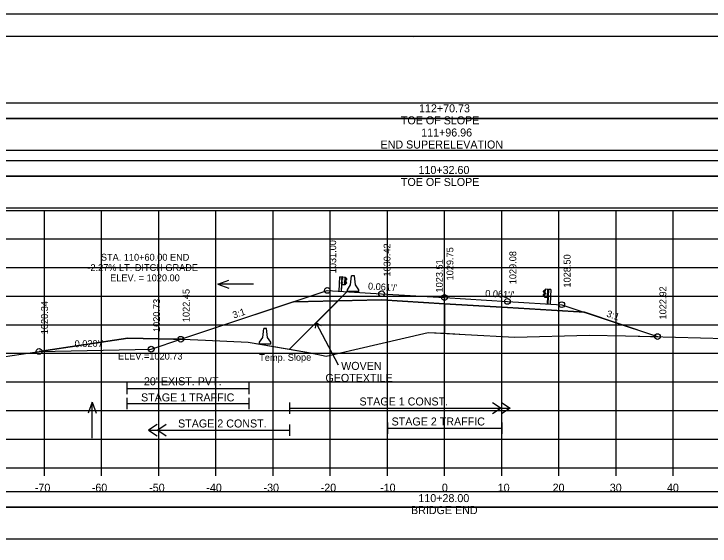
# Model space of a CAD drawing. Extents: x 1370565 to 1374448, y 301010 to 304637.
# Drawn here: x 1370659.7 to 1370781.5, y 302410.8 to 302503.9 of the extents above; entities that cross this region are included whole.
import ezdxf

# ---------------------------------------------------------------- set-up
doc = ezdxf.new("R2010")
doc.units = 0
for name, color, linetype in [('Default', 7, 'Continuous'), ('R_Alt Surface', 7, 'Continuous'), ('R_Axis', 7, 'Continuous'), ('R_Axis Annot', 7, 'Continuous'), ('R_Border', 7, 'Continuous'), ('R_Contours', 7, 'Continuous'), ('R_Drive', 7, 'Continuous'), ('R_Exist Surface', 7, 'Continuous'), ('R_Fin Surface', 7, 'Continuous'), ('R_Grid', 7, 'Continuous'), ('R_MOT', 7, 'Continuous'), ('R_No Plot', 7, 'Continuous'), ('R_Proposed Road', 7, 'Continuous'), ('R_Water', 7, 'Continuous'), ('R_Water Annot', 7, 'Continuous'), ('R_Xsect Elev', 7, 'Continuous'), ('R_Xsect Slope', 7, 'Continuous')]:
    doc.layers.add(name, color=color, linetype=linetype)

# ---------------------------------------------------------------- blocks, each defined once
blk = doc.blocks.new('MEDBAR_P')
at = {"layer": 'R_MOT'}
for p, q in [((-2.46, -0.98), (-1.63, 6.93)), ((-0.38, 6.93), (-1.63, 6.93)), ((0.87, 6.93), (-0.38, 6.93)), ((1.71, -0.98), (0.87, 6.93)), ((-5.37, -6.81), (-5.34, -5.15)), ((-5.34, -5.15), (-2.46, -0.98)), ((4.66, -5.15), (1.71, -0.98)), ((4.63, -6.81), (4.66, -5.15)), ((4.63, -6.81), (-5.37, -6.81))]:
    blk.add_line(p, q, dxfattribs=at)
blk = doc.blocks.new('GUARDRAIL LT_P')
at = {"layer": 'R_Proposed Road'}
for p, q in [((0, 2.52), (0, 0)), ((0.03, 2.52), (0.03, 0)), ((0.53, 2.52), (0.46, 2.51)), ((0.49, 0), (0.49, 2.52)), ((0.53, 2.52), (0.52, 2.52)), ((1.02, 1.15), (1.02, 2.51)), ((0.39, 1.42), (0.39, 1.51)), ((0.4, 2.11), (0.4, 2.2)), ((0.45, 1.53), (0.4, 1.53)), ((0.45, 1.49), (0.4, 1.49)), ((0.45, 1.43), (0.4, 1.43)), ((0.45, 1.43), (0.4, 1.43)), ((0.45, 1.4), (0.4, 1.4)), ((0.46, 2.21), (0.41, 2.21)), ((0.46, 2.18), (0.41, 2.18)), ((0.46, 2.12), (0.41, 2.12)), ((0.46, 2.12), (0.41, 2.12)), ((0.46, 2.09), (0.41, 2.09)), ((0.45, 1.4), (0.45, 1.53)), ((0.46, 2.09), (0.46, 2.21)), ((0.58, 2.15), (0.52, 2.15)), ((0.58, 1.46), (0.52, 1.46)), ((0.53, 2.21), (0.58, 2.21)), ((0.53, 2.08), (0.58, 2.08)), ((0.58, 1.53), (0.53, 1.53)), ((0.58, 1.4), (0.53, 1.4)), ((0.58, 2.21), (0.58, 2.08)), ((0.58, 1.4), (0.58, 1.53)), ((1.01, 1.89), (0.96, 1.89)), ((0.96, 1.78), (0.96, 1.88)), ((1.01, 1.86), (0.96, 1.86)), ((1.01, 1.8), (0.96, 1.8)), ((1.01, 1.77), (0.96, 1.77)), ((1.01, 1.8), (0.97, 1.8)), ((1.01, 1.77), (1.01, 1.89)), ((1.05, 1.31), (1.16, 1.37)), ((1.17, 2.3), (1.06, 2.36)), ((1.16, 2.29), (1.06, 2.34)), ((1.06, 1.77), (1.06, 1.9)), ((1.06, 1.29), (1.17, 1.35)), ((1.09, 1.77), (1.09, 1.9)), ((1.26, 1.6), (1.1, 1.69)), ((1.11, 1.97), (1.28, 2.07)), ((1.12, 1.95), (1.29, 2.05)), ((1.27, 1.62), (1.12, 1.71)), ((1.28, 2.18), (1.16, 2.29)), ((1.16, 1.37), (1.29, 1.48)), ((1.3, 2.2), (1.17, 2.3)), ((1.17, 1.35), (1.3, 1.46)), ((0.52, 1.15), (0.49, 1.15))]:
    blk.add_line(p, q, dxfattribs=at)
blk.add_lwpolyline([(0, 2.52), (0.46, 2.51), (0.45, 0)], dxfattribs=at)
for points in [[(1.05, 2.52), (1.05, 1.15), (0.52, 1.15), (0.53, 2.52)], [(0.39, 1.49), (0.39, 1.43), (0.36, 1.43), (0.36, 1.49)], [(0.4, 2.18), (0.4, 2.12), (0.37, 2.12), (0.37, 2.18)], [(0.44, 1.55), (0.44, 1.38), (0.45, 1.38), (0.45, 1.55)], [(0.45, 2.23), (0.45, 2.07), (0.46, 2.07), (0.46, 2.23)], [(0.58, 2.21), (0.58, 2.08), (0.53, 2.08), (0.53, 2.21)], [(0.58, 1.53), (0.58, 1.4), (0.53, 1.4), (0.53, 1.53)], [(0.95, 1.86), (0.95, 1.8), (0.93, 1.8), (0.93, 1.86)], [(1.01, 1.91), (1.01, 1.75), (1.02, 1.75), (1.02, 1.91)]]:
    blk.add_lwpolyline(points, close=True, dxfattribs=at)
for centre, radius, start, end in [((0.41, 1.51), 0.022, 134.5745, 222.2244), ((0.48, 1.46), 0.0922, 159.7423, 200.2577), ((0.41, 1.41), 0.025, 140.9334, 216.6234), ((0.42, 2.2), 0.022, 134.5745, 222.2244), ((0.49, 2.15), 0.0922, 159.7423, 200.2577), ((0.43, 2.1), 0.025, 140.9334, 216.6234), ((0.98, 1.88), 0.022, 134.5745, 222.2244), ((1.05, 1.83), 0.0922, 159.7423, 200.2577), ((0.98, 1.78), 0.025, 140.9334, 216.6234), ((1.15, 1.89), 0.0865, 118.106, 175.0444), ((1.13, 1.76), 0.0703, 171.7804, 246.8536), ((1.08, 1.83), 0.0453, 282.9554, 86.0697), ((1.15, 1.89), 0.0622, 118.106, 175.0444), ((1.13, 1.76), 0.0462, 171.7804, 246.8536), ((1.22, 1.52), 0.0854, 325.2184, 59.12), ((1.22, 1.52), 0.109, 325.2184, 59.12), ((1.25, 2.13), 0.062, 299.2499, 57.9783), ((1.25, 2.13), 0.0856, 299.2499, 57.9783)]:
    blk.add_arc(centre, radius, start, end, dxfattribs=at)
blk = doc.blocks.new('GUARDRAIL RT_P')
at = {"layer": 'R_Proposed Road'}
for p, q in [((-1.02, 1.15), (-1.02, 2.51)), ((-0.53, 2.52), (-0.52, 2.52)), ((-0.53, 2.52), (-0.46, 2.51)), ((-0.49, 0), (-0.49, 2.52)), ((-0.03, 2.52), (-0.03, 0)), ((0, 2.52), (0, 0)), ((-1.3, 2.2), (-1.17, 2.3)), ((-1.17, 1.35), (-1.3, 1.46)), ((-1.12, 1.95), (-1.29, 2.05)), ((-1.16, 1.37), (-1.29, 1.48)), ((-1.28, 2.18), (-1.16, 2.29)), ((-1.11, 1.97), (-1.28, 2.07)), ((-1.27, 1.62), (-1.12, 1.71)), ((-1.26, 1.6), (-1.1, 1.69)), ((-1.17, 2.3), (-1.06, 2.36)), ((-1.06, 1.29), (-1.17, 1.35)), ((-1.16, 2.29), (-1.06, 2.34)), ((-1.05, 1.31), (-1.16, 1.37)), ((-1.09, 1.77), (-1.09, 1.9)), ((-1.06, 1.77), (-1.06, 1.9)), ((-1.01, 1.77), (-1.01, 1.89)), ((-1.01, 1.89), (-0.96, 1.89)), ((-1.01, 1.86), (-0.96, 1.86)), ((-1.01, 1.8), (-0.97, 1.8)), ((-1.01, 1.8), (-0.96, 1.8)), ((-1.01, 1.77), (-0.96, 1.77)), ((-0.96, 1.78), (-0.96, 1.88)), ((-0.53, 2.21), (-0.58, 2.21)), ((-0.58, 2.21), (-0.58, 2.08)), ((-0.58, 2.15), (-0.52, 2.15)), ((-0.53, 2.08), (-0.58, 2.08)), ((-0.58, 1.4), (-0.58, 1.53)), ((-0.58, 1.53), (-0.53, 1.53)), ((-0.58, 1.46), (-0.52, 1.46)), ((-0.58, 1.4), (-0.53, 1.4)), ((-0.46, 2.09), (-0.46, 2.21)), ((-0.46, 2.21), (-0.41, 2.21)), ((-0.46, 2.18), (-0.41, 2.18)), ((-0.46, 2.12), (-0.41, 2.12)), ((-0.46, 2.12), (-0.41, 2.12)), ((-0.46, 2.09), (-0.41, 2.09)), ((-0.45, 1.4), (-0.45, 1.53)), ((-0.45, 1.53), (-0.4, 1.53)), ((-0.45, 1.49), (-0.4, 1.49)), ((-0.45, 1.43), (-0.4, 1.43)), ((-0.45, 1.43), (-0.4, 1.43)), ((-0.45, 1.4), (-0.4, 1.4)), ((-0.4, 2.11), (-0.4, 2.2)), ((-0.39, 1.42), (-0.39, 1.51)), ((-0.52, 1.15), (-0.49, 1.15))]:
    blk.add_line(p, q, dxfattribs=at)
for points in [[(-1.05, 2.52), (-1.05, 1.15), (-0.52, 1.15), (-0.53, 2.52)], [(-1.01, 1.91), (-1.01, 1.75), (-1.02, 1.75), (-1.02, 1.91)], [(-0.95, 1.86), (-0.95, 1.8), (-0.93, 1.8), (-0.93, 1.86)], [(-0.58, 2.21), (-0.58, 2.08), (-0.53, 2.08), (-0.53, 2.21)], [(-0.58, 1.53), (-0.58, 1.4), (-0.53, 1.4), (-0.53, 1.53)], [(-0.45, 2.23), (-0.45, 2.07), (-0.46, 2.07), (-0.46, 2.23)], [(-0.44, 1.55), (-0.44, 1.38), (-0.45, 1.38), (-0.45, 1.55)], [(-0.4, 2.18), (-0.4, 2.12), (-0.37, 2.12), (-0.37, 2.18)], [(-0.39, 1.49), (-0.39, 1.43), (-0.36, 1.43), (-0.36, 1.49)]]:
    blk.add_lwpolyline(points, close=True, dxfattribs=at)
blk.add_lwpolyline([(0, 2.52), (-0.46, 2.51), (-0.45, 0)], dxfattribs=at)
for centre, radius, start, end in [((-1.25, 2.13), 0.0856, 122.0217, 240.7501), ((-1.22, 1.52), 0.109, 120.88, 214.7816), ((-1.25, 2.13), 0.062, 122.0217, 240.7501), ((-1.22, 1.52), 0.0854, 120.88, 214.7816), ((-1.08, 1.83), 0.0453, 93.9303, 257.0446), ((-1.15, 1.89), 0.0622, 4.9556, 61.894), ((-1.15, 1.89), 0.0865, 4.9556, 61.894), ((-1.13, 1.76), 0.0462, 293.1464, 8.2196), ((-1.13, 1.76), 0.0703, 293.1464, 8.2196), ((-0.98, 1.88), 0.022, 317.7756, 45.4255), ((-1.05, 1.83), 0.0922, 339.7423, 20.2577), ((-0.98, 1.78), 0.025, 323.3766, 39.0666), ((-0.42, 2.2), 0.022, 317.7756, 45.4255), ((-0.49, 2.15), 0.0922, 339.7423, 20.2577), ((-0.43, 2.1), 0.025, 323.3766, 39.0666), ((-0.41, 1.51), 0.022, 317.7756, 45.4255), ((-0.48, 1.46), 0.0922, 339.7423, 20.2577), ((-0.41, 1.41), 0.025, 323.3766, 39.0666)]:
    blk.add_arc(centre, radius, start, end, dxfattribs=at)

msp = doc.modelspace()

# ---------------------------------------------------------------- linework, layer by layer
at = {"layer": 'R_Alt Surface'}
for points in [[(1370708.62, 302453.53), (1370724.03, 302453.84), (1370735.03, 302453.17), (1370746.03, 302452.5), (1370759.5, 302451.68)], [(1370712.49, 302448.88), (1370712.59, 302449.81), (1370713.46, 302449.34)], [(1370716.51, 302442.42), (1370712.59, 302449.81)], [(1370707.94, 302435.91), (1370707.94, 302433.91)], [(1370743.42, 302435.91), (1370744.92, 302434.91), (1370743.42, 302433.91)], [(1370745.02, 302435.91), (1370746.52, 302434.91), (1370745.02, 302433.91)], [(1370707.94, 302434.91), (1370746.52, 302434.91)], [(1370684.76, 302432.05), (1370683.26, 302431.05), (1370684.76, 302430.05)], [(1370686.36, 302432.05), (1370684.86, 302431.05), (1370686.36, 302430.05)], [(1370707.94, 302432.05), (1370707.94, 302430.05)], [(1370725.03, 302432.4), (1370725.03, 302430.4)], [(1370745.03, 302432.4), (1370745.03, 302430.4)], [(1370683.26, 302431.05), (1370707.94, 302431.05)], [(1370725.03, 302431.4), (1370745.03, 302431.4)]]:
    msp.add_lwpolyline(points, dxfattribs=at)
at = {"layer": 'R_Axis'}
for p, q in [((1370585.03, 302424.5), (1370885.03, 302424.5)), ((1370665.03, 302423.1), (1370665.03, 302424.5)), ((1370675.03, 302423.1), (1370675.03, 302424.5)), ((1370685.03, 302423.1), (1370685.03, 302424.5)), ((1370695.03, 302423.1), (1370695.03, 302424.5)), ((1370705.03, 302423.1), (1370705.03, 302424.5)), ((1370715.03, 302423.1), (1370715.03, 302424.5)), ((1370725.03, 302423.1), (1370725.03, 302424.5)), ((1370735.03, 302423.1), (1370735.03, 302424.5)), ((1370745.03, 302423.1), (1370745.03, 302424.5)), ((1370755.03, 302423.1), (1370755.03, 302424.5)), ((1370765.03, 302423.1), (1370765.03, 302424.5)), ((1370775.03, 302423.1), (1370775.03, 302424.5))]:
    msp.add_line(p, q, dxfattribs=at)
for points in [[(1370679.48, 302439.37), (1370679.48, 302437.37)], [(1370700.82, 302439.37), (1370700.82, 302437.37)], [(1370679.48, 302438.37), (1370700.82, 302438.37)], [(1370679.48, 302436.73), (1370679.48, 302434.73)], [(1370700.82, 302436.73), (1370700.82, 302434.73)], [(1370679.48, 302435.73), (1370700.82, 302435.73)]]:
    msp.add_lwpolyline(points, dxfattribs=at)
at = {"layer": 'R_Border'}
for p, q in [((1370577.03, 302499.96), (1370893.21, 302499.96)), ((1370729.55, 302499.7), (1370729.55, 302499.7)), ((1370729.55, 302499.7), (1370729.55, 302499.7))]:
    msp.add_line(p, q, dxfattribs=at)
at = {"layer": 'R_Contours'}
for p, q in [((1370708.62, 302453.53), (1370689.37, 302447.11)), ((1370716.43, 302453.69), (1370707.94, 302445.21)), ((1370707.94, 302445.21), (1370716.43, 302453.69)), ((1370716.43, 302453.69), (1370708.62, 302453.53)), ((1370735.03, 302448.02), (1370735.03, 302453.17)), ((1370735.03, 302453.17), (1370735.03, 302448.02)), ((1370771.81, 302447.58), (1370759.5, 302451.68)), ((1370688.89, 302446.96), (1370687.61, 302446.97))]:
    msp.add_line(p, q, dxfattribs=at)
for points in [[(1370735.03, 302453.17), (1370724.03, 302453.84), (1370716.43, 302453.69)], [(1370759.5, 302451.68), (1370746.03, 302452.5), (1370735.03, 302453.17)], [(1370707.94, 302445.21), (1370711.61, 302444.57), (1370714.32, 302444.01), (1370719.33, 302445.18), (1370732.16, 302448.17), (1370735.03, 302448.02)], [(1370735.03, 302448.02), (1370738.65, 302447.81), (1370747.31, 302447.33), (1370760.36, 302447.68), (1370766.68, 302447.56), (1370771.78, 302447.43)], [(1370687.61, 302446.97), (1370679.63, 302447.18), (1370664.13, 302444.84)], [(1370664.13, 302444.84), (1370683.72, 302445.23), (1370688.89, 302446.96)], [(1370689.39, 302446.95), (1370690.54, 302446.94), (1370693.24, 302446.83), (1370700.66, 302446.46), (1370707.94, 302445.21)]]:
    msp.add_lwpolyline(points, dxfattribs=at)
for centre, start, end in [((1370772.28, 302447.42), 161.5651, 178.5366), ((1370688.89, 302446.96), 359.3269, 18.4349)]:
    msp.add_arc(centre, 0.5, start, end, dxfattribs=at)
at = {"layer": 'R_Drive'}
for points in [[(1370585.23, 302485.56), (1370883.65, 302485.56), (1370883.65, 302488.27), (1370585.23, 302488.27)], [(1370585.23, 302480.04), (1370883.65, 302480.04), (1370883.65, 302485.56), (1370585.23, 302485.56)], [(1370585.23, 302475.46), (1370883.65, 302475.46), (1370883.65, 302478.17), (1370585.23, 302478.17)], [(1370585.23, 302469.94), (1370883.65, 302469.94), (1370883.65, 302475.46), (1370585.23, 302475.46)], [(1370585.82, 302417.6), (1370884.24, 302417.6), (1370884.24, 302420.3), (1370585.82, 302420.3)], [(1370585.82, 302412.08), (1370884.24, 302412.08), (1370884.24, 302417.6), (1370585.82, 302417.6)]]:
    msp.add_lwpolyline(points, close=True, dxfattribs=at)
at = {"layer": 'R_Exist Surface'}
msp.add_lwpolyline([(1370585.03, 302448.71), (1370585.75, 302448.68), (1370589.95, 302448.49), (1370647.79, 302445.6), (1370648.37, 302445.52), (1370657.82, 302443.86), (1370664.13, 302444.84), (1370679.63, 302447.18), (1370687.61, 302446.97), (1370690.54, 302446.94), (1370693.24, 302446.83), (1370700.66, 302446.46), (1370711.61, 302444.57), (1370714.32, 302444.01), (1370719.33, 302445.18), (1370732.16, 302448.17), (1370738.65, 302447.81), (1370747.31, 302447.33), (1370760.36, 302447.68), (1370766.68, 302447.56), (1370784.21, 302447.12)], dxfattribs=at)
at = {"layer": 'R_Fin Surface'}
msp.add_line((1370718.03, 302455.29), (1370707.94, 302445.21), dxfattribs=at)
msp.add_lwpolyline([(1370664.11, 302444.84), (1370683.72, 302445.23), (1370688.89, 302446.96), (1370714.53, 302455.5), (1370724.03, 302454.92), (1370735.03, 302454.25), (1370746.03, 302453.58), (1370755.53, 302453.01), (1370772.28, 302447.42)], dxfattribs=at)
at = {"layer": 'R_Grid'}
for p, q in [((1370585.03, 302469.5), (1370885.03, 302469.5)), ((1370665.03, 302424.5), (1370665.03, 302469.5)), ((1370675.03, 302424.5), (1370675.03, 302469.5)), ((1370685.03, 302424.5), (1370685.03, 302469.5)), ((1370695.03, 302424.5), (1370695.03, 302469.5)), ((1370705.03, 302424.5), (1370705.03, 302469.5)), ((1370715.03, 302424.5), (1370715.03, 302469.5)), ((1370725.03, 302424.5), (1370725.03, 302469.5)), ((1370735.03, 302424.5), (1370735.03, 302469.5)), ((1370745.03, 302424.5), (1370745.03, 302469.5)), ((1370755.03, 302424.5), (1370755.03, 302469.5)), ((1370765.03, 302424.5), (1370765.03, 302469.5)), ((1370775.03, 302424.5), (1370775.03, 302469.5)), ((1370585.03, 302464.5), (1370885.03, 302464.5)), ((1370585.03, 302459.5), (1370885.03, 302459.5)), ((1370585.03, 302454.5), (1370885.03, 302454.5)), ((1370585.03, 302449.5), (1370885.03, 302449.5)), ((1370585.03, 302444.5), (1370885.03, 302444.5)), ((1370585.03, 302439.5), (1370885.03, 302439.5)), ((1370585.03, 302434.5), (1370885.03, 302434.5)), ((1370585.03, 302429.5), (1370885.03, 302429.5)), ((1370585.03, 302424.5), (1370885.03, 302424.5))]:
    msp.add_line(p, q, dxfattribs=at)
at = {"layer": 'R_No Plot'}
msp.add_line((1370564.63, 302503.86), (1370897.96, 302503.86), dxfattribs=at)
for points in [[(1370564.62, 302503.86), (1370897.96, 302503.86), (1370897.96, 302290.52), (1370564.62, 302290.52)], [(1370810.95, 302499.96), (1370830.57, 302499.96), (1370830.57, 302490.08), (1370846.68, 302490.08), (1370869.88, 302490.08), (1370869.88, 302457.41), (1370893.09, 302457.41), (1370893.21, 302294.5), (1370577.03, 302294.5), (1370577.03, 302499.96)]]:
    msp.add_lwpolyline(points, close=True, dxfattribs=at)
for centre in [(1370714.53, 302455.5), (1370714.53, 302455.5), (1370724.03, 302454.92), (1370735.03, 302454.25), (1370746.03, 302453.58), (1370755.53, 302453.01), (1370755.53, 302453.01), (1370688.89, 302446.96), (1370772.28, 302447.42), (1370664.11, 302444.84), (1370683.72, 302445.23)]:
    msp.add_circle(centre, 0.5, dxfattribs=at)
at = {"layer": 'R_Water Annot'}
for p, q in [((1370695.36, 302456.61), (1370697.28, 302457.31)), ((1370701.64, 302456.61), (1370695.36, 302456.61)), ((1370695.36, 302456.61), (1370697.28, 302455.91)), ((1370673.4, 302435.94), (1370672.7, 302434.01)), ((1370673.4, 302429.65), (1370673.4, 302435.94)), ((1370673.4, 302435.94), (1370674.1, 302434.01))]:
    msp.add_line(p, q, dxfattribs=at)
at = {"layer": 'R_Xsect Elev'}
msp.add_line((1370735.03, 302448.02), (1370735.03, 302461.39), dxfattribs=at)

# ---------------------------------------------------------------- block references
at = {"layer": 'Default'}
for name, p, rotation in [('GUARDRAIL LT_P', (1370716.52, 302455.38), -2.79108977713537), ('GUARDRAIL RT_P', (1370753.53, 302453.13), -2.8654870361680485)]:
    msp.add_blockref(name, p, dxfattribs=dict(at, rotation=rotation))
at = {"layer": 'R_Fin Surface', "xscale": 0.2, "yscale": 0.20000000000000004}
for p in [(1370719.1, 302456.65), (1370703.74, 302447.48)]:
    msp.add_blockref('MEDBAR_P', p, dxfattribs=at)

# ---------------------------------------------------------------- texts
at = {"layer": 'R_Axis Annot'}
for s, p in [('112+70.73', (1370730.57, 302486.65)), ('TOE OF SLOPE', (1370727.4, 302484.55)), ('111+96.96', (1370730.95, 302482.42)), ('END SUPERELEVATION', (1370723.84, 302480.32)), ('110+32.60', (1370730.48, 302475.87)), ('TOE OF SLOPE', (1370727.4, 302473.77)), ('WOVEN ', (1370716.95, 302441.6)), ("20' EXIST. PVT.", (1370682.45, 302438.92)), ('GEOTEXTILE', (1370714.2, 302439.5)), ('-70', (1370663.37, 302420.3)), ('-60', (1370673.33, 302420.3)), ('-50', (1370683.37, 302420.3)), ('-40', (1370693.37, 302420.3)), ('-30', (1370703.37, 302420.3)), ('-20', (1370713.37, 302420.3)), ('-10', (1370723.76, 302420.3)), ('0', (1370734.57, 302420.3)), ('10', (1370744.34, 302420.3)), ('20', (1370753.94, 302420.3)), ('30', (1370763.94, 302420.3)), ('40', (1370773.94, 302420.3)), ('110+28.00', (1370730.46, 302418.48)), ('BRIDGE END', (1370729.17, 302416.38))]:
    msp.add_text(s, height=1.4, dxfattribs=at).set_placement(p)
at = {"layer": 'R_Water'}
for s, p in [('STAGE 1 TRAFFIC', (1370681.94, 302436.09)), ('STAGE 1 CONST.', (1370720.16, 302435.38)), ('STAGE 2 CONST.', (1370688.42, 302431.53)), ('STAGE 2 TRAFFIC', (1370725.77, 302431.88))]:
    msp.add_text(s, height=1.4, dxfattribs=at).set_placement(p)
at = {"layer": 'R_Xsect Elev'}
for s, p in [('1031.00', (1370716.08, 302458.5)), ('1030.42', (1370725.58, 302457.92)), ('1029.75', (1370736.58, 302457.25)), ('1029.08', (1370747.58, 302456.58)), ('1023.51', (1370734.73, 302455.14)), ('1028.50', (1370757.08, 302456.01)), ('1022.92', (1370773.83, 302450.42)), ('1022.45', (1370690.44, 302449.96)), ('1020.34', (1370665.66, 302447.84)), ('1020.73', (1370685.27, 302448.23))]:
    msp.add_text(s, height=1.2, rotation=90, dxfattribs=at).set_placement(p)
for s, p in [('STA. 110+60.00 END ', (1370674.92, 302460.7)), ('-2.27% LT. DITCH GRADE', (1370672.56, 302458.9)), ('ELEV. = 1020.00', (1370676.54, 302457.1)), ('ELEV.=1020.73', (1370677.91, 302443.41))]:
    msp.add_text(s, height=1.2, dxfattribs=at).set_placement(p)
at = {"layer": 'R_Xsect Slope'}
for s, rotation, p in [("0.061'/'", 356.5193, (1370721.62, 302455.67)), ("0.061'/'", 356.5193, (1370742.12, 302454.42)), ('3:1', 18.4349, (1370698.18, 302450.58)), ('3:1', 341.5651, (1370763.27, 302450.95)), ("0.020'/'", 1.1458, (1370670.34, 302445.56)), ('Temp. Slope', 0.3453, (1370702.62, 302443.16))]:
    msp.add_text(s, height=1.2, rotation=rotation, dxfattribs=at).set_placement(p)

doc.saveas('drawing.dxf')
